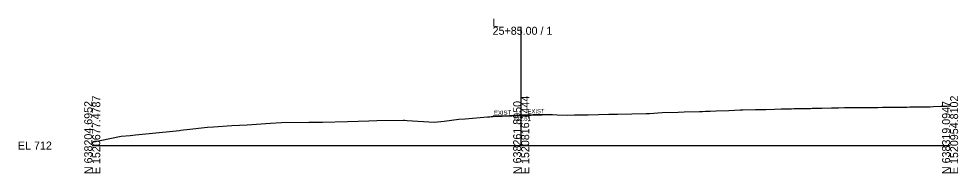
# Model space of a CAD drawing. Extents: x -26 to 3903, y -10 to 9531.
# Drawn here: x 3574.3 to 3902.8, y -9.7 to 44.4 of the extents above; entities that cross this region are included whole.
import ezdxf

# ---------------------------------------------------------------- set-up
doc = ezdxf.new("R2010")
doc.units = 0
for name, color, linetype in [('Exist Cross Section Cell', 7, 'Continuous'), ('Exist XS Center Line Elevation Label', 7, 'Continuous'), ('Exist XS Ground Line', 7, 'Continuous'), ('Prop CMT Pvmt Surface', 7, 'Continuous'), ('Prop CMT Pvmt Surface Shoulder', 7, 'Continuous'), ('Prop CMT Subgrade Earthwork', 7, 'Continuous'), ('Prop XS Earthwork Shape', 7, 'Continuous'), ('Prop XS SE Text', 7, 'Continuous')]:
    doc.layers.add(name, color=color, linetype=linetype)

msp = doc.modelspace()

# ---------------------------------------------------------------- linework, layer by layer
at = {"layer": 'Exist Cross Section Cell'}
for p, q in [((3750, 0), (3750, 41.59)), ((3600, 0), (3750, 0)), ((3750, 0), (3900, 0))]:
    msp.add_line(p, q, dxfattribs=at)
at = {"layer": 'Exist XS Ground Line'}
msp.add_lwpolyline([(3600, 1.2), (3602.72, 1.77), (3610.1, 3.28), (3613.2, 3.47), (3615.18, 3.74), (3628.19, 5.04), (3630.51, 5.31), (3630.93, 5.35), (3631.87, 5.45), (3633.08, 5.61), (3640.31, 6.4), (3642.35, 6.59), (3648.84, 6.99), (3654.23, 7.29), (3662.29, 7.85), (3666.22, 8.09), (3675.74, 8.14), (3680.56, 8.21), (3689.28, 8.41), (3696.72, 8.62), (3699.5, 8.73), (3708.74, 8.86), (3709.25, 8.87), (3710.08, 8.81), (3719.63, 8.18), (3723.1, 8.54), (3728.19, 9.18), (3730.47, 9.31), (3738.23, 10.03), (3739, 10.1), (3739.46, 10.13), (3740.2, 10.19), (3741.73, 10.24), (3742.18, 10.26), (3742.99, 10.3), (3744.89, 10.39), (3745.68, 10.43), (3747.6, 10.53), (3749.51, 10.6), (3750.3, 10.62), (3752.19, 10.67), (3752.99, 10.69), (3754.14, 10.72), (3755.79, 10.76), (3756.55, 10.79), (3757.32, 10.81), (3758.38, 10.83), (3760, 10.86), (3760.46, 10.87), (3761.01, 10.85), (3762.59, 10.78), (3766.03, 10.67), (3768.62, 10.7), (3773.43, 10.77), (3780.63, 10.94), (3781.65, 10.97), (3783.63, 11.01), (3793.74, 11.26), (3794.93, 11.28), (3799.32, 11.53), (3804.87, 11.68), (3806.98, 11.76), (3812.39, 11.92), (3813.4, 11.97), (3814.5, 12.01), (3816.1, 12.07), (3818.15, 12.14), (3822.65, 12.33), (3826.62, 12.46), (3827.49, 12.49), (3831.9, 12.62), (3834.83, 12.67), (3835.54, 12.68), (3838.57, 12.75), (3840.96, 12.81), (3841.33, 12.82), (3842.78, 12.86), (3844.5, 12.9), (3845.4, 12.92), (3848.23, 12.97), (3848.88, 12.98), (3851.13, 13.03), (3851.72, 13.04), (3852.51, 13.07), (3853.6, 13.1), (3855.14, 13.13), (3858.56, 13.21), (3859.92, 13.22), (3861.01, 13.24), (3863.05, 13.28), (3864.26, 13.29), (3865.27, 13.29), (3866.45, 13.28), (3866.75, 13.28), (3868.59, 13.29), (3869.3, 13.3), (3870.11, 13.3), (3872.1, 13.32), (3874.69, 13.35), (3876.33, 13.39), (3877.47, 13.42), (3878.09, 13.42), (3880.75, 13.47), (3883.27, 13.47), (3885.03, 13.49), (3885.97, 13.5), (3887.31, 13.52), (3888.28, 13.53), (3888.68, 13.53), (3890.2, 13.55), (3891.39, 13.56), (3891.92, 13.59), (3892.56, 13.6), (3893.09, 13.61), (3894.24, 13.65), (3896.79, 13.74), (3898.87, 13.82), (3899.49, 13.85), (3900, 13.86)], dxfattribs=at)
at = {"layer": 'Prop CMT Pvmt Surface'}
for p, q in [((3740.19, 10.25), (3740.05, 10.17)), ((3740.19, 10.25), (3750, 10.69)), ((3760.35, 10.9), (3760.4, 10.86))]:
    msp.add_line(p, q, dxfattribs=at)
at = {"layer": 'Prop CMT Pvmt Surface Shoulder'}
msp.add_line((3760.35, 10.9), (3750, 10.69), dxfattribs=at)
at = {"layer": 'Prop CMT Subgrade Earthwork'}
msp.add_line((3750, 10.69), (3750, 10.56), dxfattribs=at)
msp.add_lwpolyline([(3740.05, 10.17), (3750, 10.56), (3760.4, 10.86)], dxfattribs=at)
at = {"layer": 'Prop XS Earthwork Shape'}
for points in [[(3740.19, 10.25), (3740.05, 10.17), (3741.73, 10.24)], [(3740.19, 10.25), (3740.05, 10.17), (3741.73, 10.24)], [(3744.89, 10.39), (3745.68, 10.43), (3747.6, 10.53), (3749.51, 10.6), (3750, 10.69), (3750, 10.56), (3741.73, 10.24), (3742.18, 10.26), (3742.99, 10.3)], [(3750, 10.69), (3750, 10.56), (3741.73, 10.24), (3742.18, 10.26), (3742.99, 10.3), (3744.89, 10.39), (3745.68, 10.43), (3747.6, 10.53), (3749.51, 10.6)], [(3750, 10.56), (3757.79, 10.82), (3756.55, 10.79), (3755.79, 10.76), (3754.14, 10.72), (3752.99, 10.69), (3752.19, 10.67), (3750.3, 10.62), (3750, 10.69)], [(3750, 10.69), (3750, 10.56), (3757.79, 10.82), (3756.55, 10.79), (3755.79, 10.76), (3754.14, 10.72), (3752.99, 10.69), (3752.19, 10.67), (3750.3, 10.62)], [(3757.32, 10.81), (3757.79, 10.82), (3756.55, 10.79)], [(3756.55, 10.79), (3757.32, 10.81), (3757.79, 10.82)]]:
    msp.add_lwpolyline(points, close=True, dxfattribs=at)

# ---------------------------------------------------------------- texts
at = {"layer": 'Exist Cross Section Cell'}
for s, p in [('L', (3740, 41.59)), ('25+85.00 / 1', (3740, 38.79)), ('EL 712', (3574, -1.4))]:
    msp.add_text(s, height=2.8, dxfattribs=at).set_placement(p)
for s, p in [('E 1520677.4787', (3602.8, -10)), ('E 1520816.1444', (3752.8, -10)), ('E 1520954.8102', (3902.8, -10)), ('N 638204.6952', (3600, -10)), ('N 638261.8950', (3750, -10)), ('N 638319.0947', (3900, -10))]:
    msp.add_text(s, height=2.8, rotation=90, dxfattribs=at).set_placement(p)
at = {"layer": 'Exist XS Center Line Elevation Label'}
msp.add_text('722.61', height=1.5, dxfattribs=at).set_placement((3747.03, 8.61))
at = {"layer": 'Prop XS SE Text'}
for p in [(3740.52, 10.67), (3752.22, 11.2)]:
    msp.add_text('EXIST', height=1.5, rotation=1.1458, dxfattribs=at).set_placement(p)

doc.saveas('drawing.dxf')
